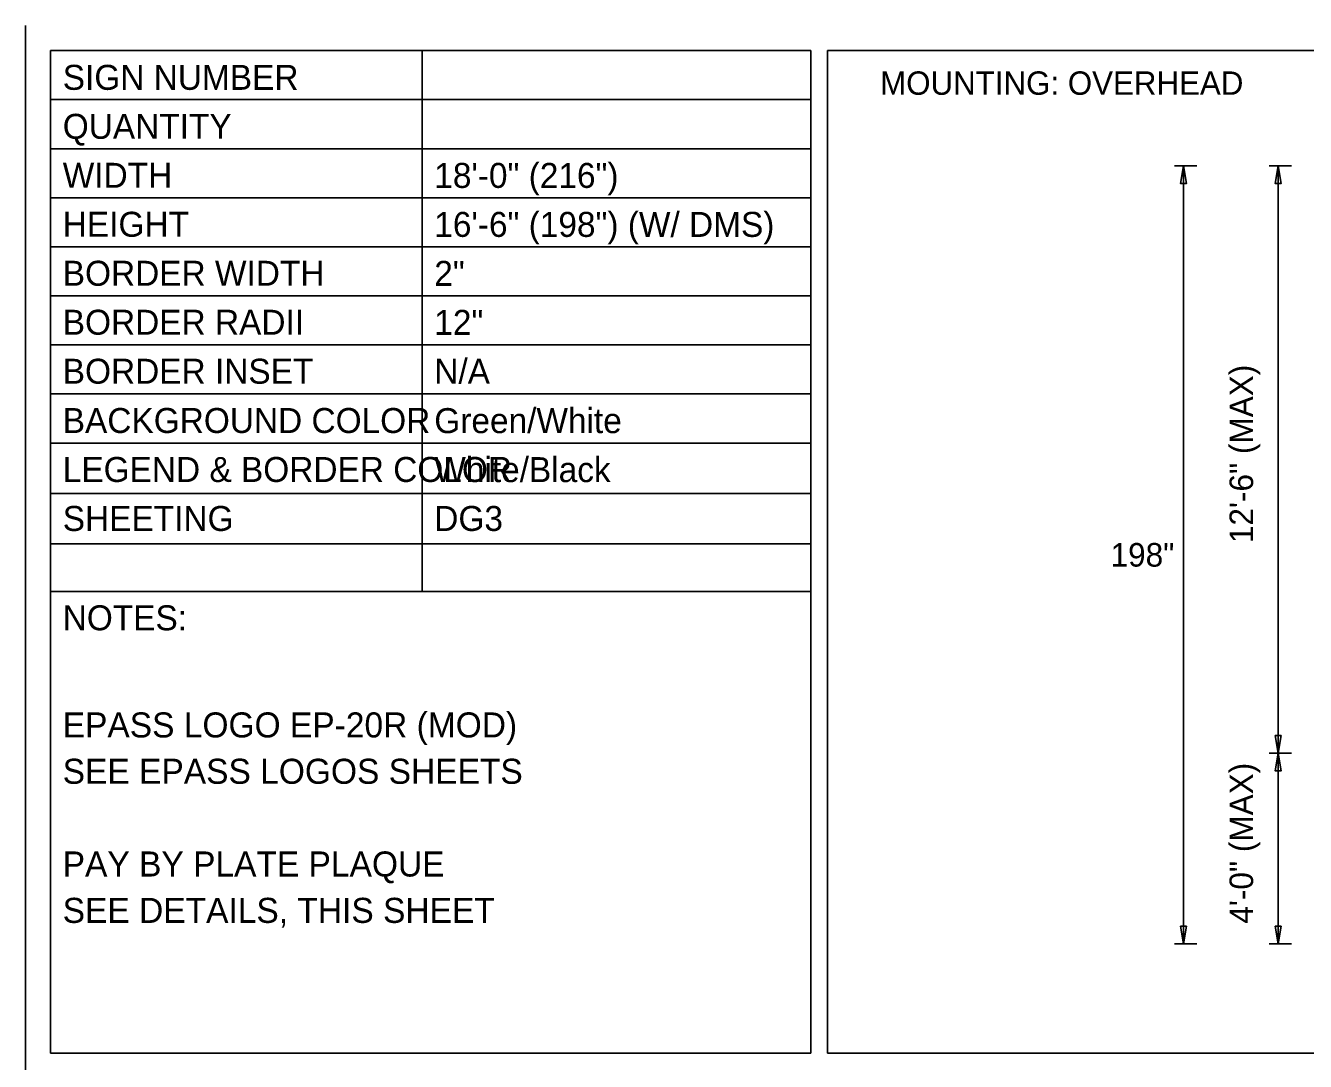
# Model space of a CAD drawing. Extents: x 10268312 to 10268472, y 2142583 to 2142688.
# Drawn here: x 10268394.73 to 10268433.03, y 2142657.28 to 2142688.28 of the extents above; entities that cross this region are included whole.
import ezdxf

# ---------------------------------------------------------------- set-up
doc = ezdxf.new("R2010")
doc.units = 0
for name, color, linetype in [('GSDims', 7, 'Continuous'), ('SheetBorder_dp', 7, 'Continuous'), ('SumBoxLines_dp', 7, 'Continuous'), ('TextMisc', 7, 'Continuous')]:
    doc.layers.add(name, color=color, linetype=linetype)

msp = doc.modelspace()

# ---------------------------------------------------------------- linework, layer by layer
at = {"layer": 'GSDims'}
for p, q in [((10268429.774, 2142684.084), (10268429.113, 2142684.084)), ((10268429.377, 2142660.8), (10268429.377, 2142684.084)), ((10268432.606, 2142684.084), (10268431.944, 2142684.084)), ((10268432.209, 2142666.504), (10268432.209, 2142684.084)), ((10268432.606, 2142666.504), (10268431.944, 2142666.504)), ((10268432.209, 2142660.8), (10268432.209, 2142666.504)), ((10268429.774, 2142660.8), (10268429.113, 2142660.8)), ((10268432.606, 2142660.8), (10268431.944, 2142660.8))]:
    msp.add_line(p, q, dxfattribs=at)
for points in [[(10268429.377, 2142684.084), (10268429.465, 2142683.555), (10268429.289, 2142683.555)], [(10268432.209, 2142684.084), (10268432.297, 2142683.555), (10268432.121, 2142683.555)], [(10268432.209, 2142666.504), (10268432.297, 2142667.033), (10268432.121, 2142667.033)], [(10268432.209, 2142666.504), (10268432.297, 2142665.975), (10268432.121, 2142665.975)], [(10268429.377, 2142660.8), (10268429.465, 2142661.329), (10268429.289, 2142661.329)], [(10268432.209, 2142660.8), (10268432.297, 2142661.329), (10268432.121, 2142661.329)]]:
    msp.add_lwpolyline(points, close=True, dxfattribs=at)
at = {"layer": 'SheetBorder_dp'}
msp.add_line((10268394.73, 2142688.282), (10268394.73, 2142592.282), dxfattribs=at)
at = {"layer": 'SumBoxLines_dp'}
for p, q in [((10268395.48, 2142687.532), (10268395.48, 2142657.532)), ((10268395.48, 2142687.532), (10268418.23, 2142687.532)), ((10268406.598, 2142687.528), (10268406.598, 2142671.345)), ((10268418.23, 2142687.532), (10268418.23, 2142657.532)), ((10268418.73, 2142687.532), (10268418.73, 2142657.532)), ((10268418.73, 2142687.532), (10268470.98, 2142687.532)), ((10268395.48, 2142686.066), (10268418.23, 2142686.066)), ((10268395.48, 2142684.59), (10268418.23, 2142684.59)), ((10268395.48, 2142683.125), (10268418.23, 2142683.125)), ((10268395.48, 2142681.659), (10268418.23, 2142681.659)), ((10268395.48, 2142680.193), (10268418.23, 2142680.193)), ((10268395.48, 2142678.727), (10268418.23, 2142678.727)), ((10268395.48, 2142677.261), (10268418.23, 2142677.261)), ((10268395.48, 2142675.786), (10268418.23, 2142675.786)), ((10268395.48, 2142674.281), (10268418.23, 2142674.281)), ((10268395.48, 2142672.776), (10268418.23, 2142672.776)), ((10268395.478, 2142671.345), (10268418.229, 2142671.345)), ((10268395.48, 2142657.532), (10268418.23, 2142657.532)), ((10268418.73, 2142657.532), (10268470.98, 2142657.532))]:
    msp.add_line(p, q, dxfattribs=at)

# ---------------------------------------------------------------- texts
at = {"layer": 'GSDims'}
msp.add_text('MOUNTING: OVERHEAD ', height=0.7, dxfattribs=at).set_placement((10268420.3, 2142686.211))
for s, height, rotation, p in [('12\'-6" (MAX)', 0.70558, 90, (10268431.461, 2142672.793)), ('198"', 0.7056, 360, (10268427.195, 2142672.09)), ('4\'-0" (MAX)', 0.70558, 90, (10268431.461, 2142661.404))]:
    msp.add_text(s, height=height, rotation=rotation, dxfattribs=at).set_placement(p)
at = {"layer": 'TextMisc'}
for s, height, p in [('SIGN NUMBER', 0.74756, (10268395.842, 2142686.359)), ('QUANTITY', 0.7476, (10268395.842, 2142684.893)), ('WIDTH', 0.7476, (10268395.842, 2142683.427)), ('18\'-0" (216")', 0.74756, (10268406.959, 2142683.424)), ('HEIGHT', 0.7476, (10268395.842, 2142681.962)), ('16\'-6" (198") (W/ DMS)', 0.74756, (10268406.959, 2142681.958)), ('BORDER WIDTH', 0.74756, (10268395.842, 2142680.496)), ('2"', 0.7476, (10268406.959, 2142680.492)), ('BORDER RADII', 0.74756, (10268395.842, 2142679.03)), ('12"', 0.7476, (10268406.959, 2142679.026)), ('N/A', 0.7476, (10268406.959, 2142677.561)), ('BORDER INSET', 0.74756, (10268395.842, 2142677.564)), ('BACKGROUND COLOR', 0.74756, (10268395.842, 2142676.089)), ('Green/White', 0.74756, (10268406.959, 2142676.085)), ('LEGEND & BORDER COLOR', 0.74756, (10268395.842, 2142674.623)), ('White/Black', 0.74756, (10268406.959, 2142674.619)), ('SHEETING', 0.7476, (10268395.842, 2142673.157)), ('DG3', 0.7476, (10268406.959, 2142673.157)), ('NOTES:', 0.7476, (10268395.84, 2142670.184)), ('EPASS LOGO EP-20R (MOD)', 0.75, (10268395.84, 2142666.977)), ('SEE EPASS LOGOS SHEETS', 0.75, (10268395.84, 2142665.59)), ('PAY BY PLATE PLAQUE', 0.75, (10268395.84, 2142662.815)), ('SEE DETAILS, THIS SHEET', 0.75, (10268395.84, 2142661.427))]:
    msp.add_text(s, height=height, dxfattribs=at).set_placement(p)

doc.saveas('drawing.dxf')
